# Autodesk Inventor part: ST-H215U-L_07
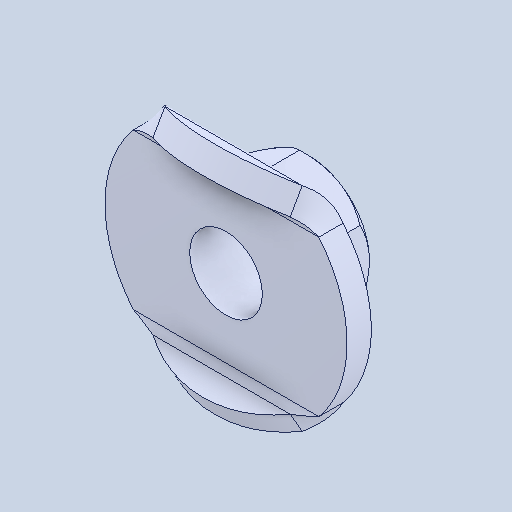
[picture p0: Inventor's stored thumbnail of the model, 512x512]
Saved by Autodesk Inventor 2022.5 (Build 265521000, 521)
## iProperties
Created: 2024-07
Part Number: ST-H215U-L_07
Material: 一般
Document SubType Name: Modeling
Designer: ImaoCorp
Density: 1 g/cm^3
Appearance: 既定
Author: ImaoCorp
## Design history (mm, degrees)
feature "ST-H215U-L_07"
node "ソリッド1"
